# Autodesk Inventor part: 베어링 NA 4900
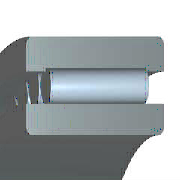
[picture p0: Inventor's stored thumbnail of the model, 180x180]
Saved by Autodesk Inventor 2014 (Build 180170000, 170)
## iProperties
Created: 2009-02
Part Number: 베어링 NA 4900
Material: Steel, Mild
Description: 니들 롤러 베어링 - 경계 치수 및 공차
Document SubType Name: Modeling
Standard: KS B 2029
Designer: SeoGD™
Standards Organization: KS
Language: ko-KR
Size Designation: NA 4900 - 10 x 22 x 13
Categories: <MemberInstance><Categories><Category DisplayName="샤프트 부품" InternalName="7f7aeb1f-a693-4053-b835-cee3144e0d98" Mnemonic="SHFT"><Category DisplayName="베어링" Inter
Density: 1 g/cm^3
Appearance: Metal-Steel
IsCustomPart: 0
Author: SeoGD™
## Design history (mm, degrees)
sketch "스케치"
  geometry: L1 (1.857, 9)-(11.143, 9); L2 (11.143, 9)-(11.143, 7); L3 (13, 7)-(0, 7); L4 (1.857, 7)-(1.857, 9); L5 (1.857, 8)-(11.143, 8); L6 (6.5, 8)-(6.5, 7); L7 (0, 5)-(13, 5); L8 (0, 11)-(13, 11); L9 (13, 5)-(13, 7); L10 (13, 8.8)-(13, 11); L11 (1.857, 8.8)-(0, 8.8); L12 (11.143, 8.8)-(13, 8.8); L13 (-6, 0)-(36, 0) reference; L14 (0, -1.9)-(0, 14.9) reference
  constraints: 24 end point, 8 point on line, 3 midpoint, 3 parallel, 3 perpendicular, 2 symmetric about line, 1 horizontal, 1 other
  dimensions: "d6" = 10 diameter of L7 L13 (= WD); "d7" = 14 diameter of L3 L13 (= KID1); "d8" = 22 diameter of L8 L13 (= BD); "d9" = 16 diameter of L6.start L13 (= 0.5 x WD + 0.5 x BD); "d10" = 17.6 diameter of L12 L13 (= 0.9 x BD + 0.9 x WD - 0.8 x KID1); "d11" = 18 diameter of L1 L13 (= BD + WD - KID1); "d12" = 1.85714 distance between parallel lines of L14 L4 (= 0.142857 x KB); "d13" = 13 distance between parallel lines of L14 L9 (= KB); "d14" = 11.14286 distance between parallel lines of L14 L2 (= 0.857143 x KB)
revolve "본체" stored, may be unused: angle "d17" = 90 deg
revolve "롤러" stored, may be unused: angle "d18" = 90 deg
pattern_circular "IDS_ARRAYROLLER[SIMPL:T]" dims angle "d2" = 360 deg
body "Solid1"
fillet "모깎기1" dims "d0" = 0.3 (= KRS)
other parameters: "WD" = 10 [user parameter; used in 6 equation terms], "BD" = 22 [user parameter; used in 6 equation terms], "KB" = 13 [user parameter; used in 3 equation terms], "KID1" = 14 [user parameter; used in 4 equation terms], "KRS" = 0.3 [user parameter; used in 1 equation term], "d3" = 0, "d4" = 0, "d5" = 0, "d15" = 0, "d16" = 0, "BC0" = 9150000 [user parameter], "WR" = 5 (= 0.5 x WD) [user parameter], "BBA" = 0 [user parameter], "BC" = 8150000 [user parameter], "BR" = 11 (= 0.5 x BD) [user parameter]
